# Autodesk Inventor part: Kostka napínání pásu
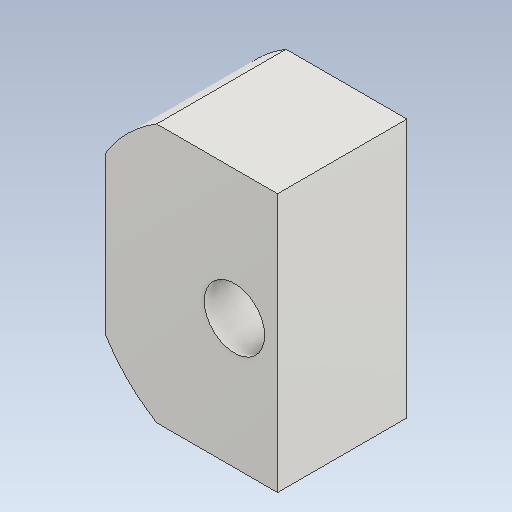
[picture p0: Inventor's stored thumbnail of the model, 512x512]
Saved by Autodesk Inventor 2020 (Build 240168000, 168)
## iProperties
Created: 2025-03
Part Number: Kostka napínání pásu
Material: Ocel
Document SubType Name: Modeling
Designer: doma
Density: 7.85 g/cm^3
Appearance: Ocel
Mass: 500.734 g
Surface Area: 111.614 cm^2
Volume: 63.7878 cm^3
Author: doma
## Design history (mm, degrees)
sketch "Náčrt1"
  geometry: L1 (-30, -30)-(30, -30); L2 (30, -30)-(30, 30); L3 (30, 30)-(-30, 30); L4 (-30, 30)-(-30, -30); L5 (-30, -30)-(30, 30); L6 (30, -30)-(-30, 30); C1 r 35 at (0, 0); 10 further points
  constraints: 12 end point, 2 coincident, 2 midpoint, 2 parallel, 1 centre point, 1 horizontal, 1 perpendicular
  dimensions: "d2" = 60 distance of L3.end L2.end; "d3" = 60 distance of L2.end L1.end; "d4" = 70 diameter of C1
extrude "Vysunutí1" new body sketch "Náčrt1" distance "d5" = 30; taper "d6" = 0 deg
extrude "Vysunutí2" cut sketch "Náčrt1" distance "d7" = 30; taper "d8" = 0 deg
sketch "Náčrt2"
  geometry: L1 (-62.122, 47.35)-(-10, 47.35); L2 (-10, 47.35)-(-10, -44.414); L3 (-10, -44.414)-(-62.122, -44.414); L4 (-62.122, -44.414)-(-62.122, 47.35); 1 further point
  constraints: 8 end point, 2 parallel, 1 horizontal, 1 perpendicular
  dimensions: "d9" = 10 distance from line of point (0, 0) L2
extrude "Vysunutí3" cut sketch "Náčrt2" distance "d10" = 30; taper "d11" = 0 deg
hole "Díra1" sketch "Náčrt1" diameter "d12" = 14; stored, may be unused: countersink angle "d16" = 90 deg, drill point angle "d18" = 118 deg; dims "d13" = 6, "d14" = 4, "d15" = 2, "d17" = 15
node "Těleso1"
